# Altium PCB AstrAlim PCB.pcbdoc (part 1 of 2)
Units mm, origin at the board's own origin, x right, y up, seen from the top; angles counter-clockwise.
Board outline 123.28 x 79.48 mm, 4 copper layers (Top Layer, Inner1, Inner2, Bottom Layer); 156 components, 74 nets, 482 pads, 222 vias.
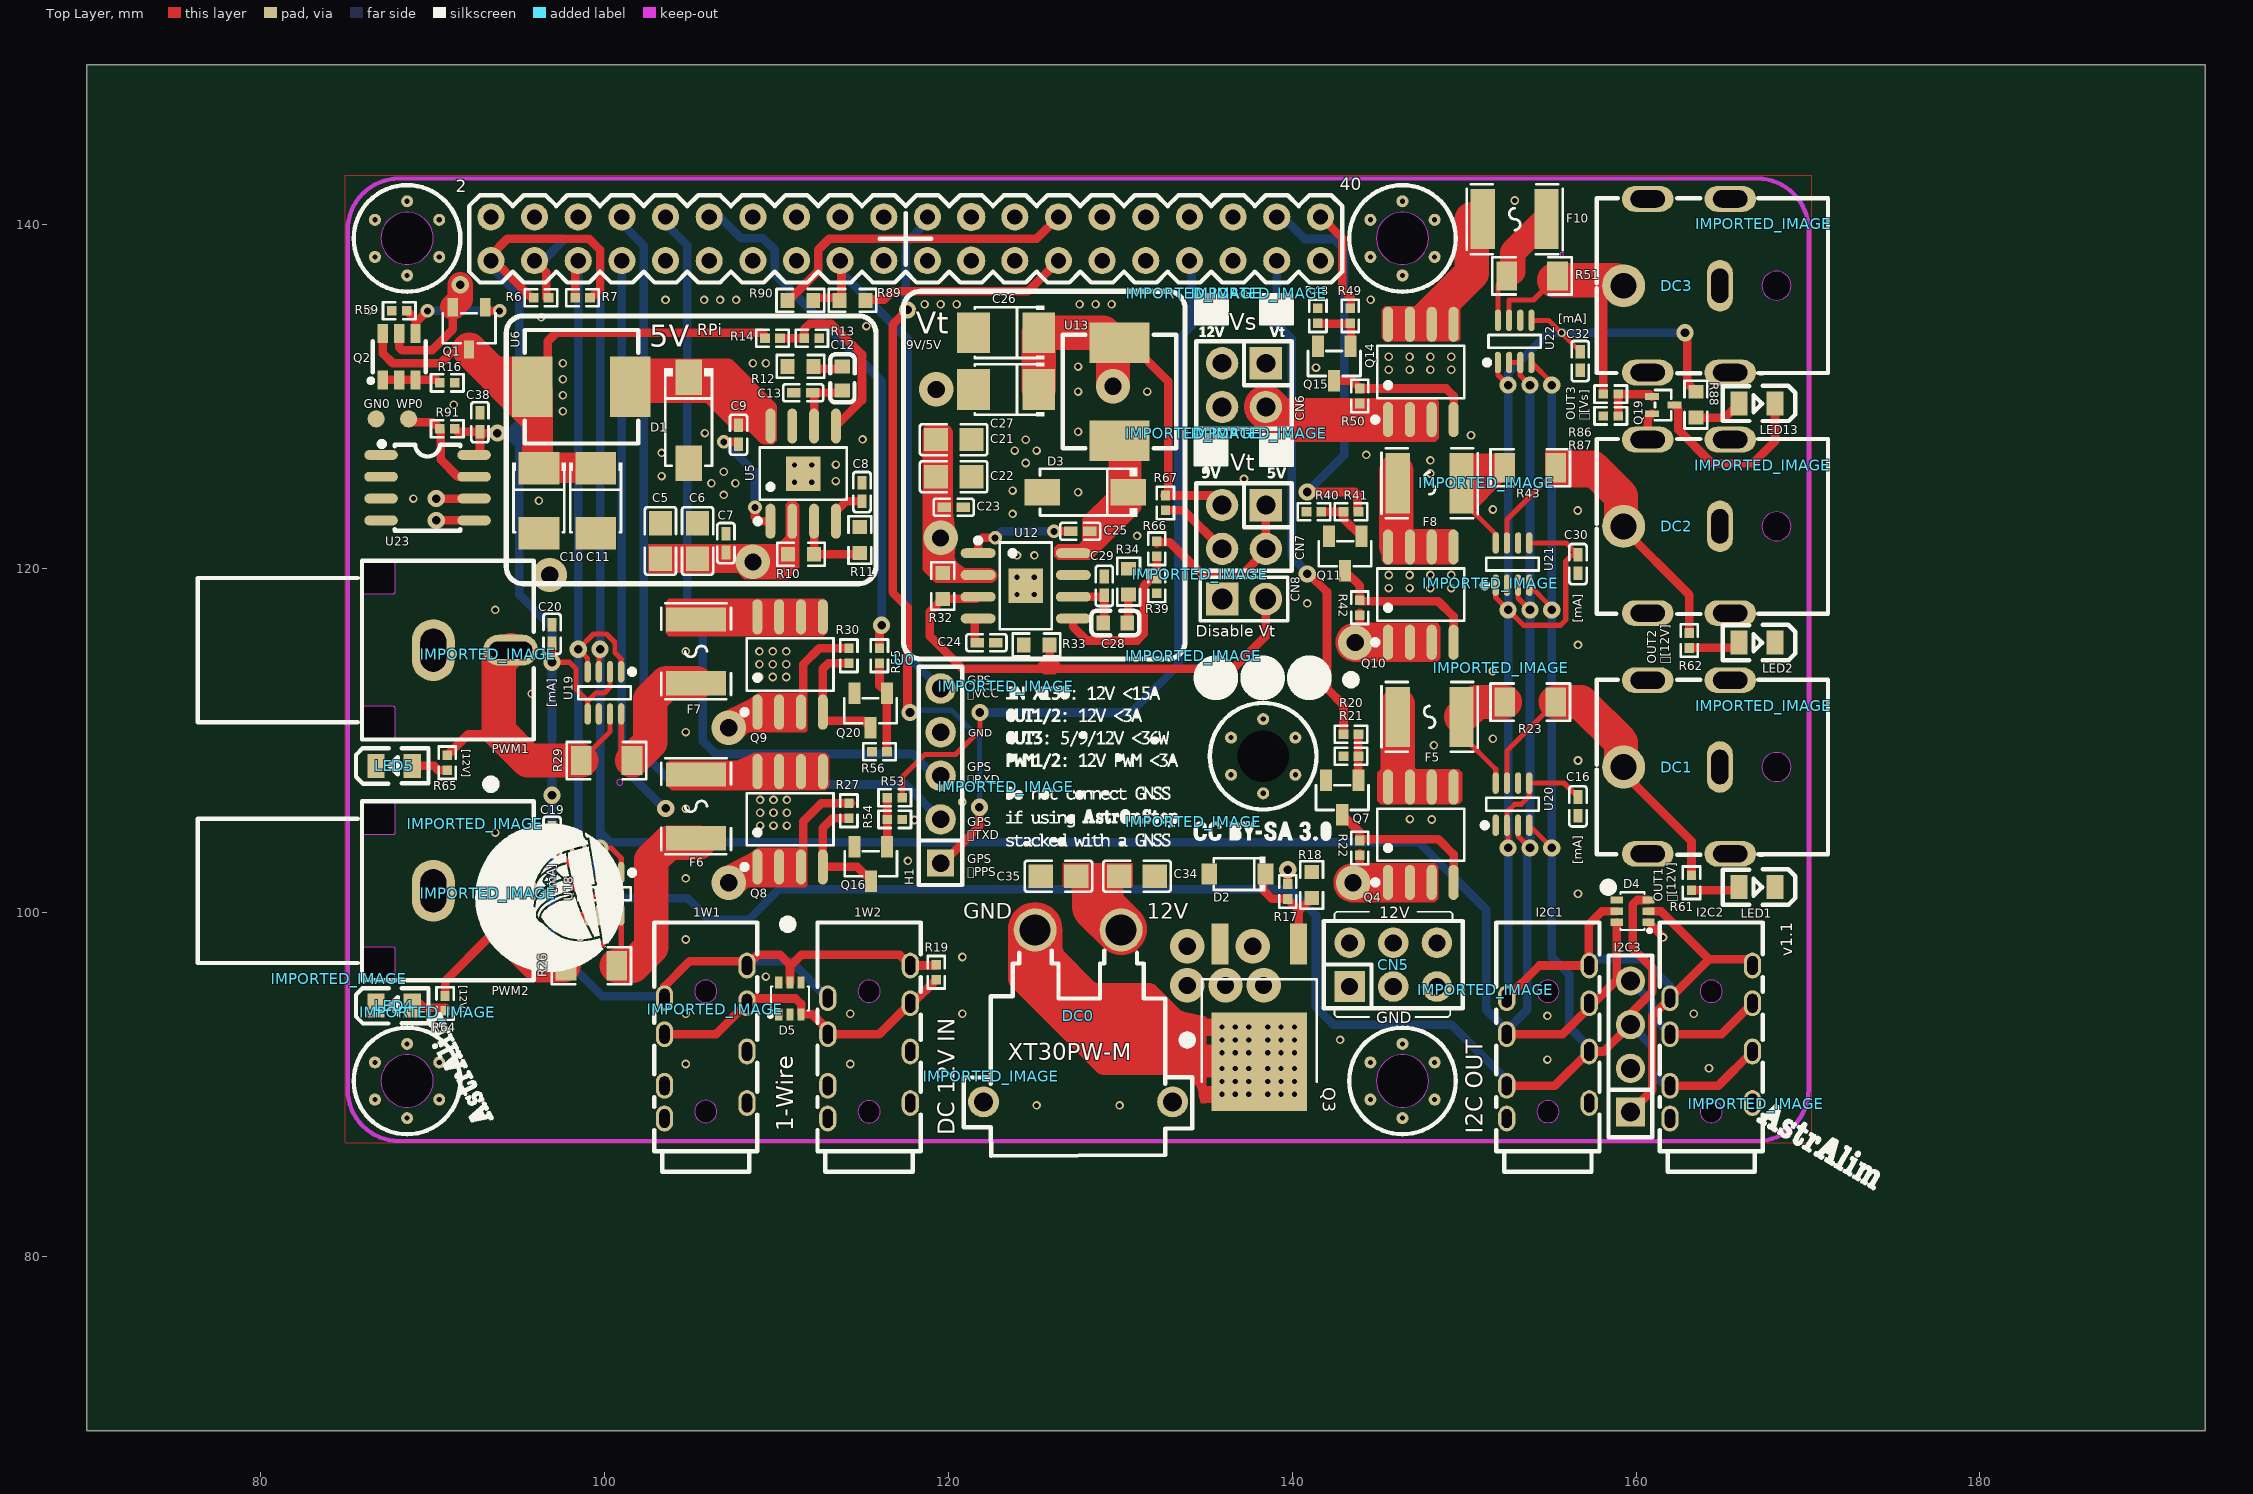
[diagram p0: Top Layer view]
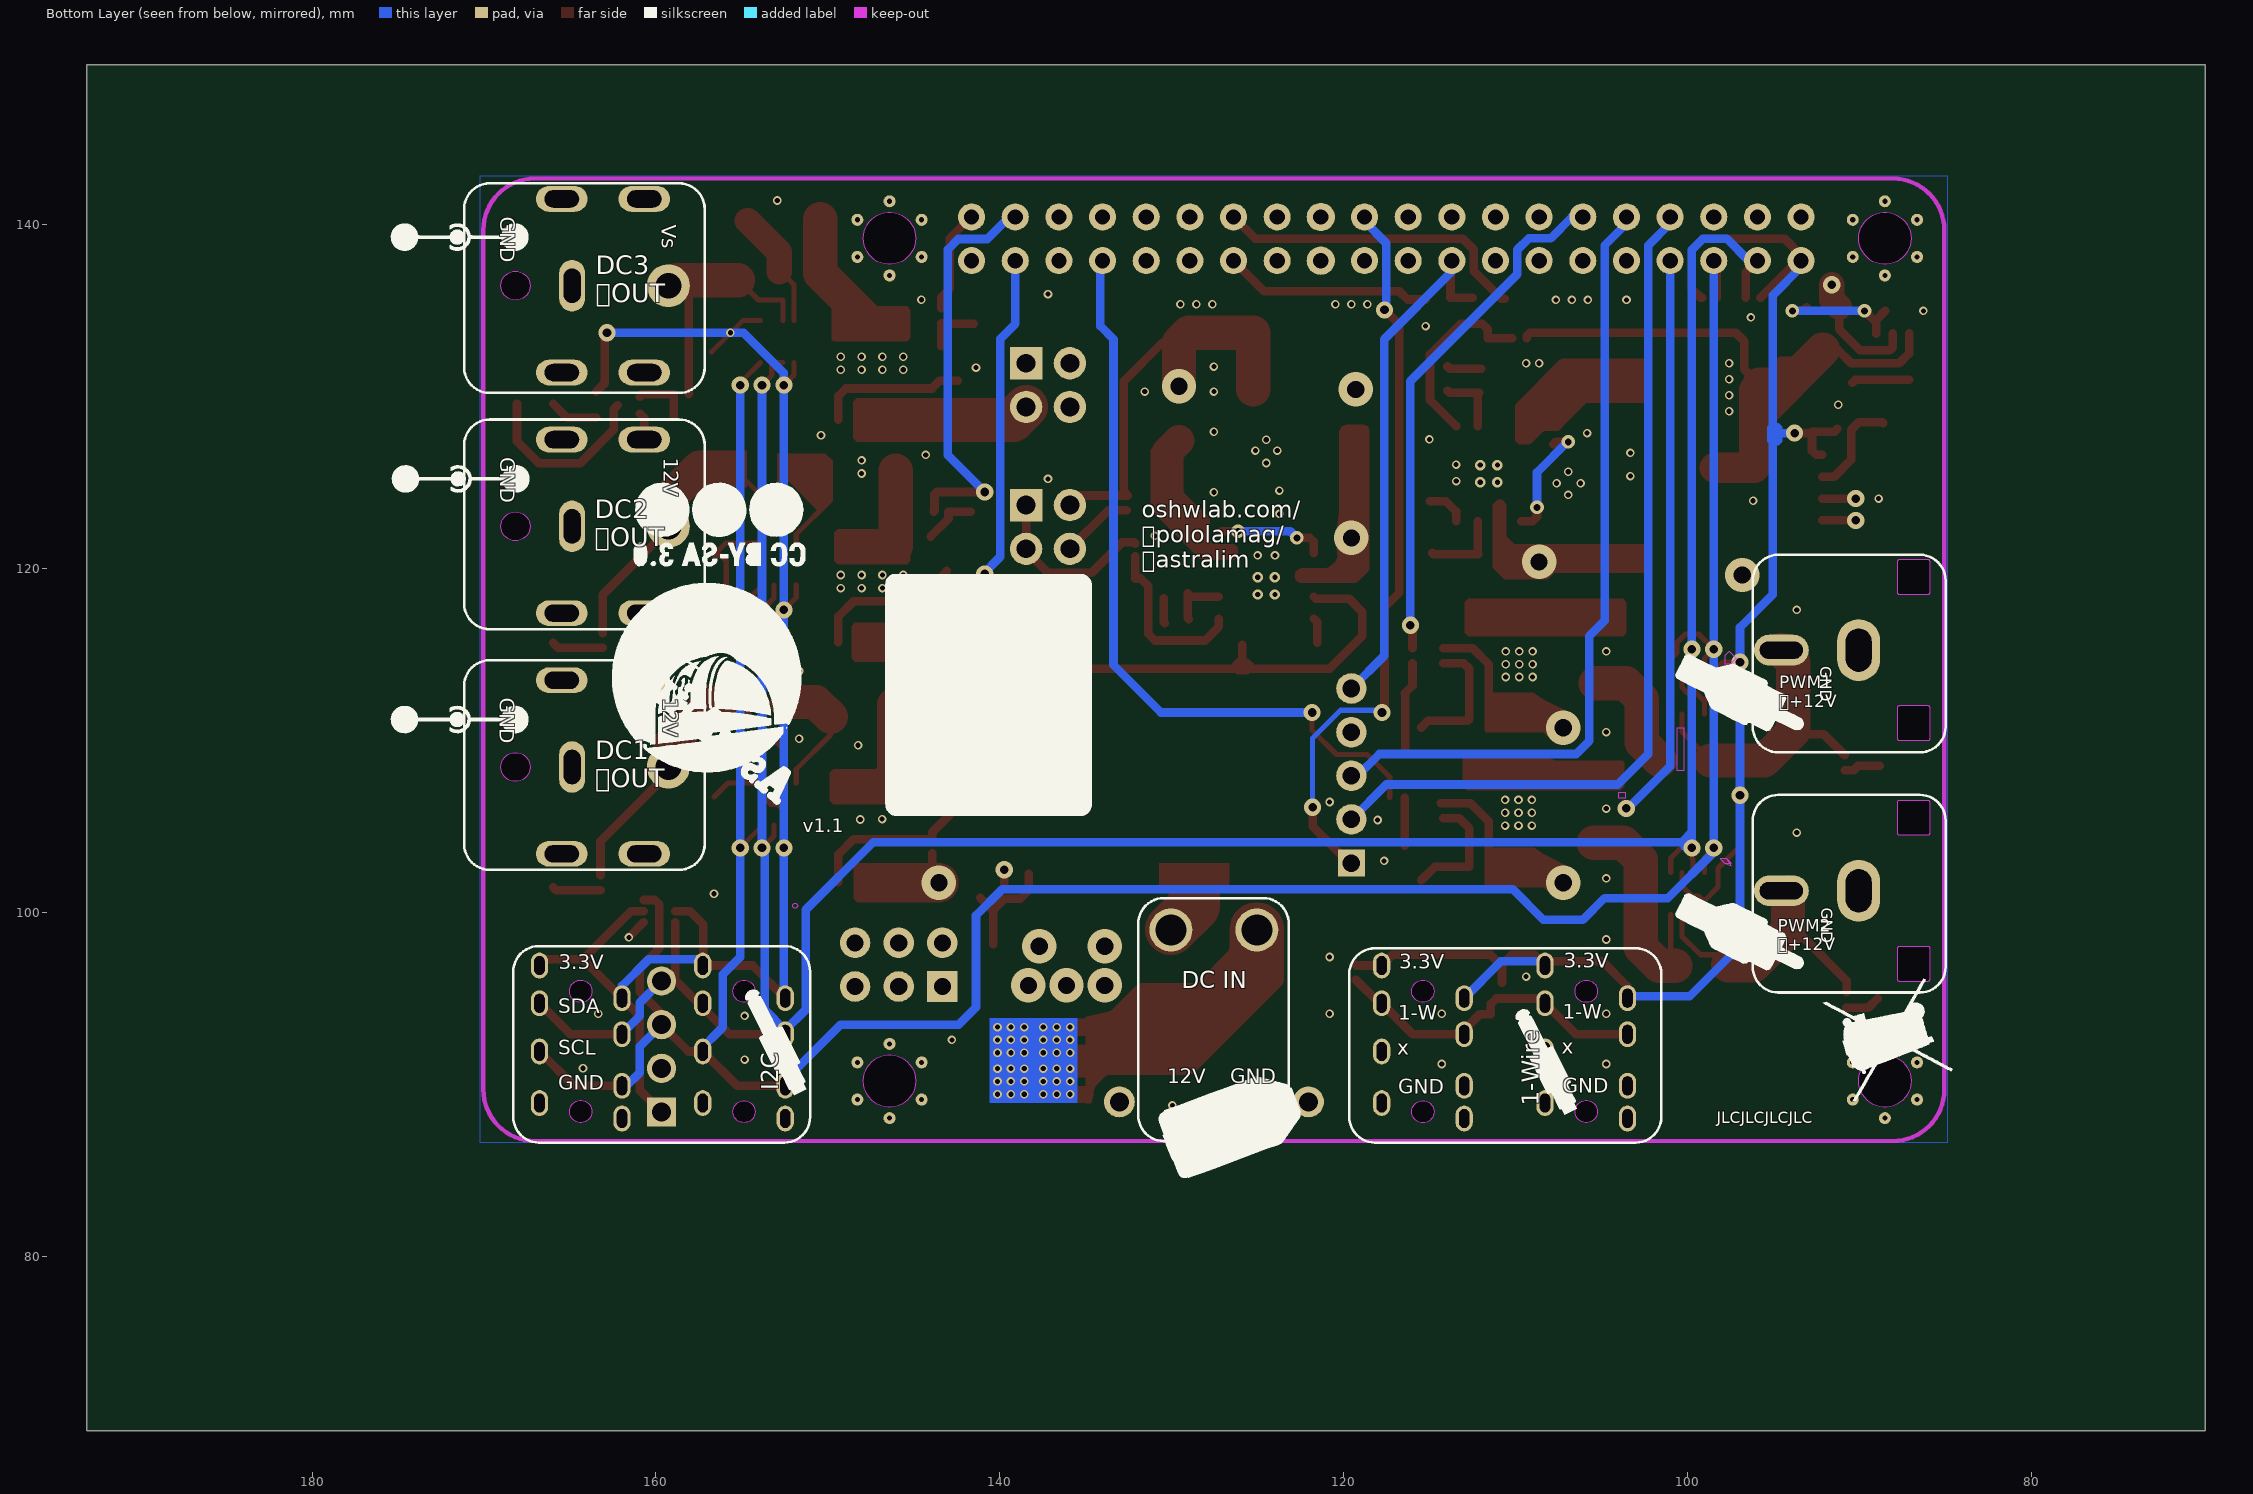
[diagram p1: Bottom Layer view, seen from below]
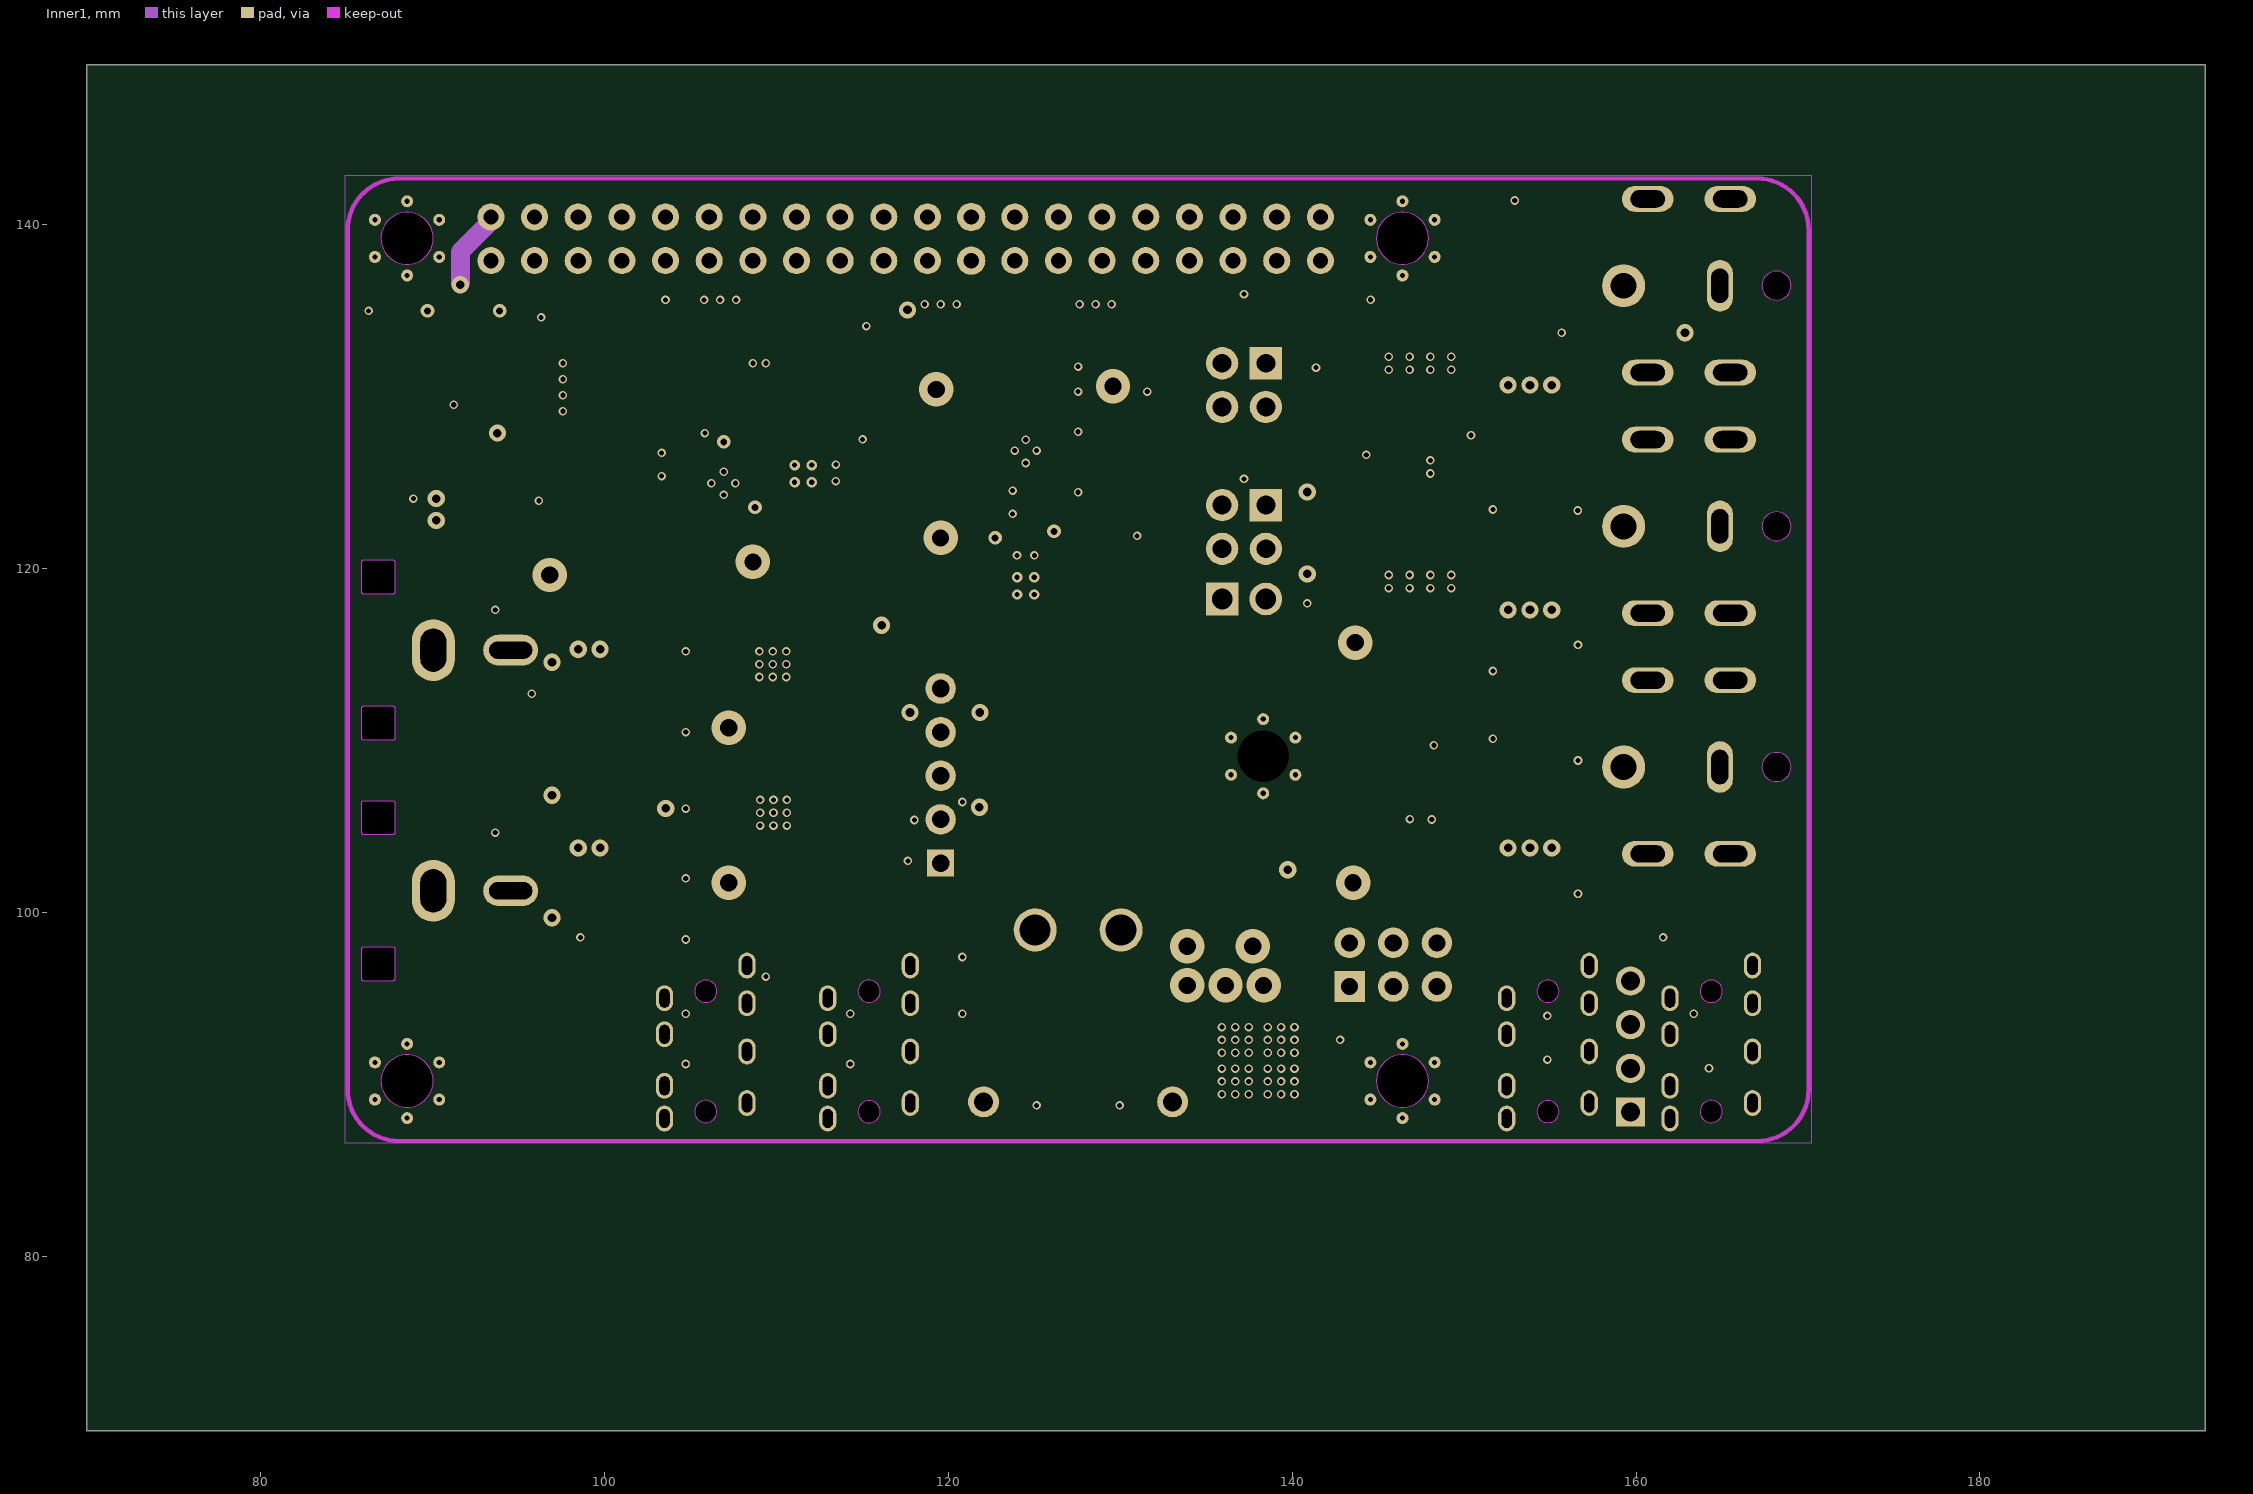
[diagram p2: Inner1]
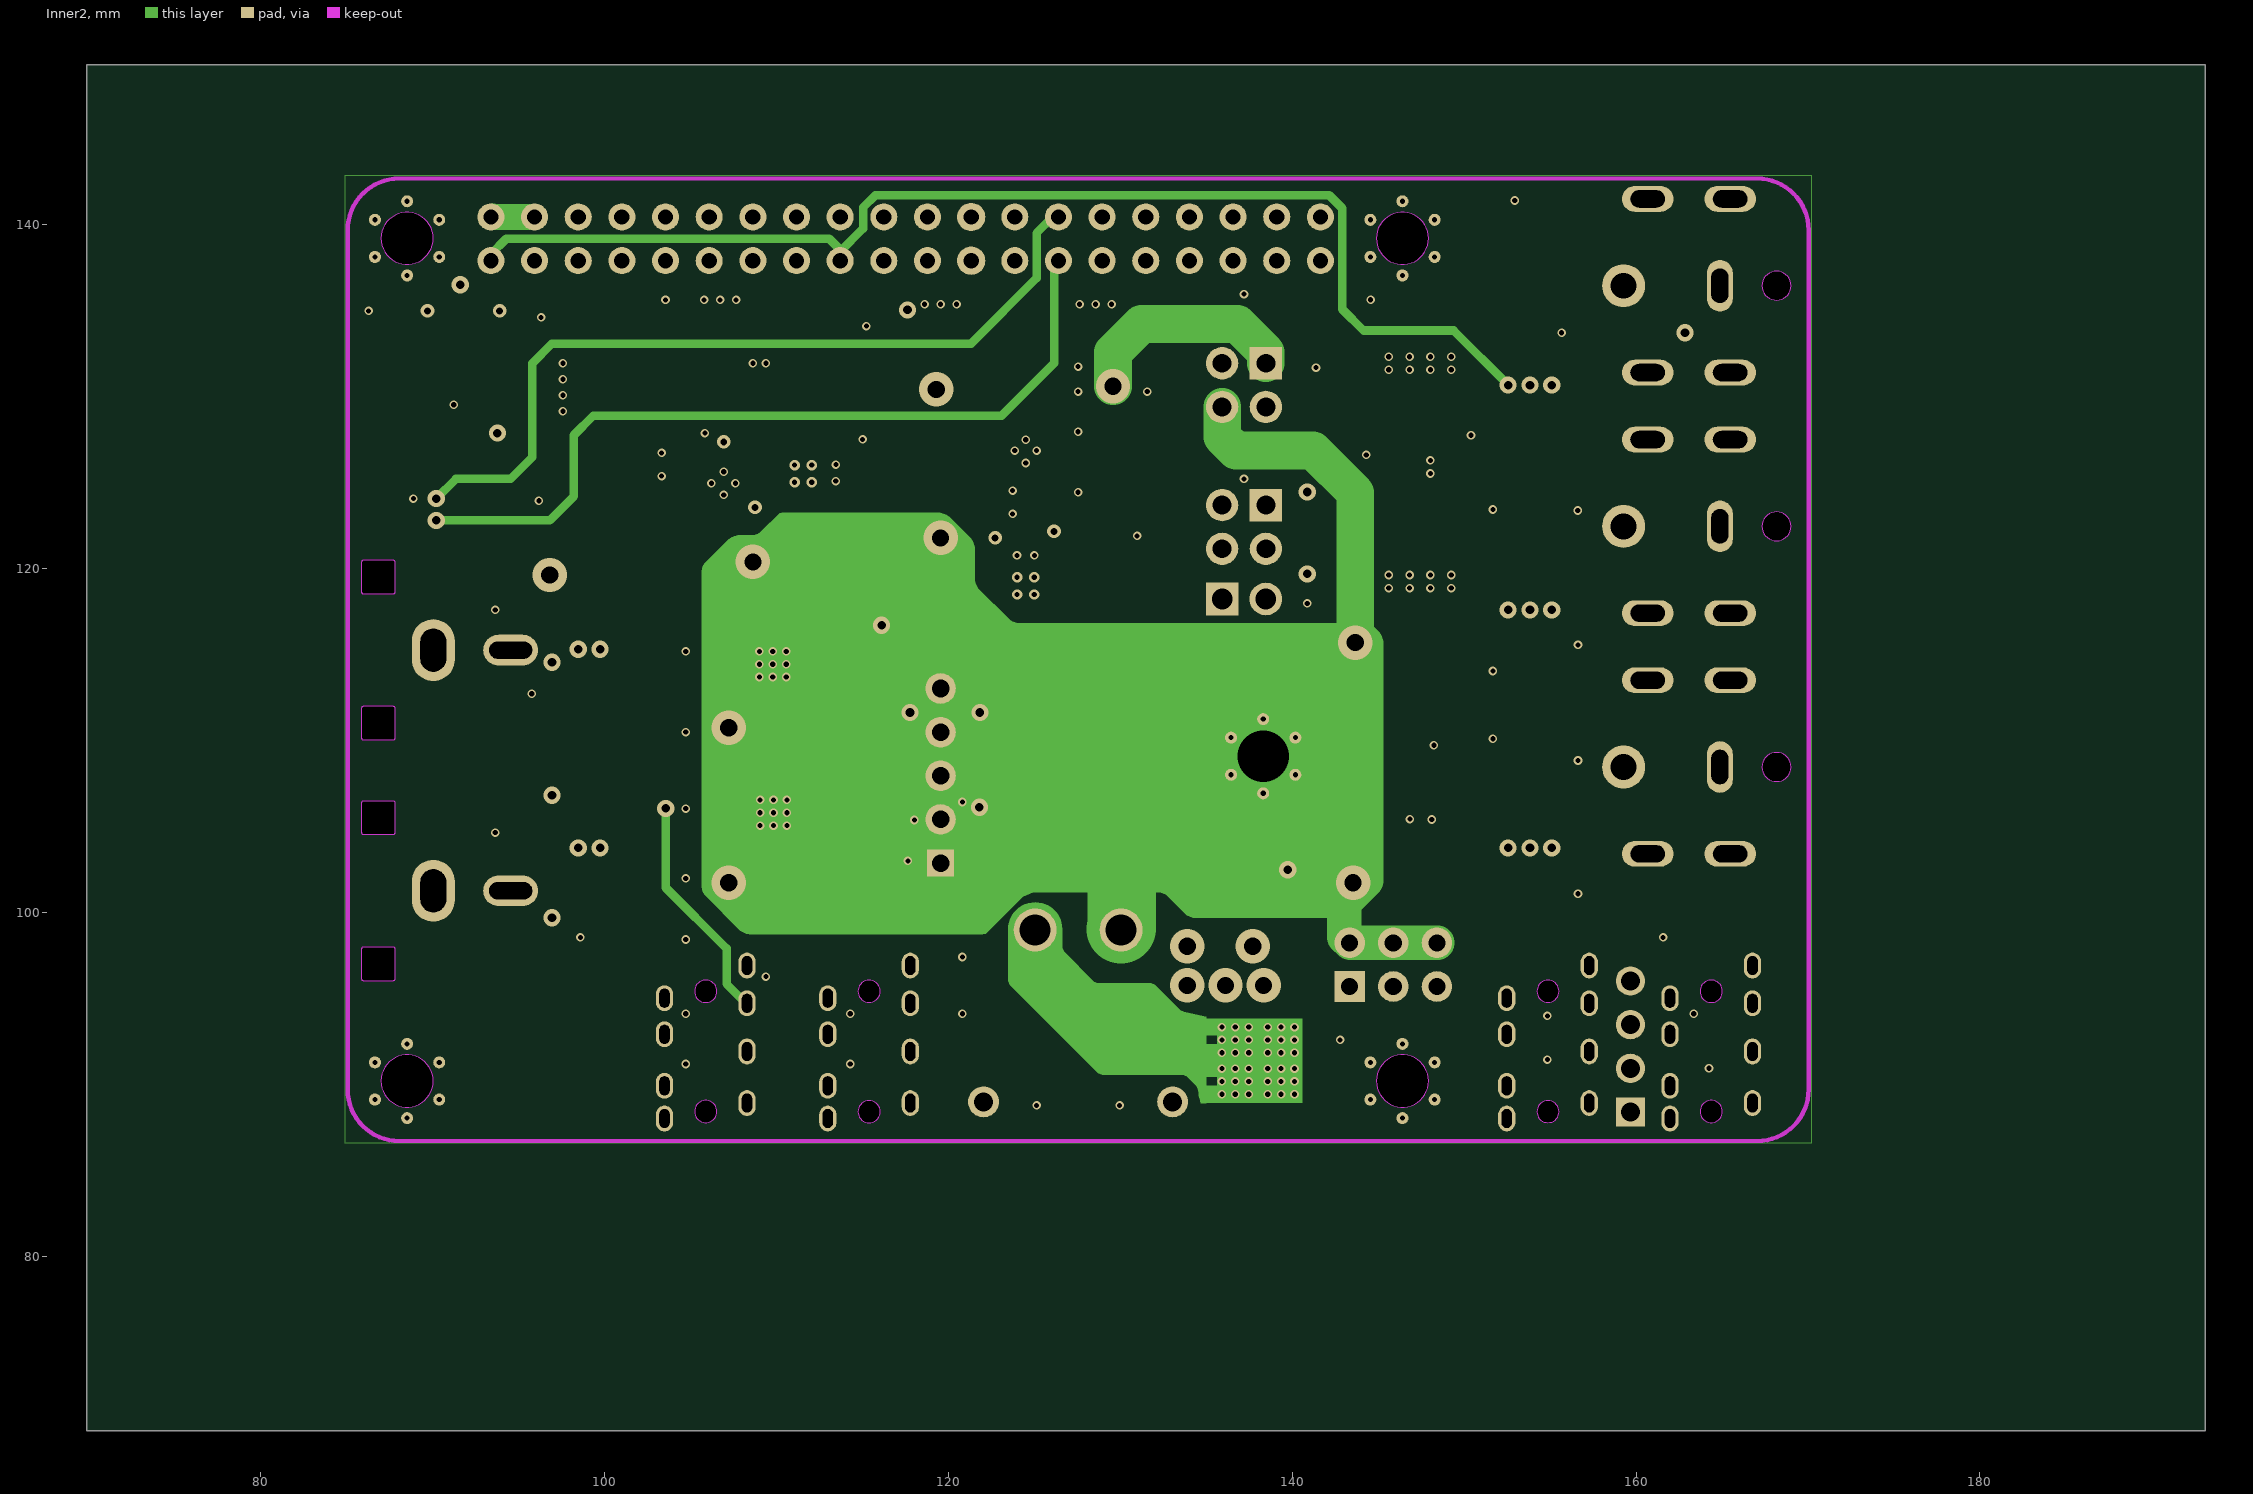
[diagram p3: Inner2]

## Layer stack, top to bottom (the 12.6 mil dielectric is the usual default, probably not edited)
Top Layer: signal copper (thickness not stored)
Dielectric: dielectric 0.32, FR-4, Dk 4.8
Inner1: signal copper (thickness not stored)
Dielectric: dielectric 0.32, FR-4, Dk 4.8
Inner2: signal copper (thickness not stored)
Dielectric: dielectric 0.32, FR-4, Dk 4.8
Bottom Layer: signal copper (thickness not stored)

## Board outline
193.13,69.85 69.85,69.85 69.85,149.333 193.13,149.333

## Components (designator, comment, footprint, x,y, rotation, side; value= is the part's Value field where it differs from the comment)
1W1 "PJ-35372" audio-th_pj-35372 105.877,92.462 r180 top
1W2 "PJ-35372" audio-th_pj-35372 115.377,92.462 r180 top
C5 "CL21A475KAQNNNE" C0805 103.242,121.614 r270 top
C6 "CL21A475KAQNNNE" C0805 105.401,121.614 r270 top
C7 "CL05B103KB5NNNC" C0402 107.052,121.487 r270 top
C8 "CL05B103KB5NNNC" C0402 114.967,124.46 r270 top
C9 "CL05B103KB5NNNC" C0402 107.784,127.793 r90 top
C10 "CA45-B-16V-47uF-K" CAP-SMD_L3.5-W2.8-R-RD 96.171,123.952 r90 top
C11 "CA45-B-16V-47uF-K" CAP-SMD_L3.5-W2.8-R-RD 99.473,123.952 r90 top
C12 "0603B222K500NT" C0603 113.824,131.064 r270 top
C13 "0402CG220J500NT" C0402 111.546,130.23 r0 top
C16 "CL05B104KO5NNNC" C0402 156.623,106.172 r270 top
C19 "CL05B104KO5NNNC" C0402 96.933,104.394 r90 top
C20 "CL05B104KO5NNNC" C0402 96.933,116.205 r90 top
C21 "CL21A475KAQNNNE" C0805 120.301,127.508 r180 top
C22 "CL21A475KAQNNNE" C0805 120.301,125.349 r180 top
C23 "CL05B103KB5NNNC" C0402 120.301,123.571 r180 top
C24 "CL05B103KB5NNNC" C0402 122.206,115.697 r180 top
C25 "CL05B103KB5NNNC" C0402 127.667,122.174 r0 top
C26 "CA45-B-16V-47uF-K" CAP-SMD_L3.5-W2.8-R-RD 123.349,133.731 r0 top
C27 "CA45-B-16V-47uF-K" CAP-SMD_L3.5-W2.8-R-RD 123.349,130.429 r0 top
C28 "0603B222K500NT" C0603 129.699,116.84 r180 top
C29 "0402CG220J500NT" C0402 129.064,118.999 r270 top
C30 "CL05B104KO5NNNC" C0402 156.623,120.269 r270 top
C32 "CL05B104KO5NNNC" C0402 156.75,132.08 r270 top
C34 "CL21A226MAQNNNE_C45783" C0805 130.969,102.108 r180 top
C35 "CL21A226MAQNNNE_C45783" C0805 126.397,102.108 r0 top
C38 "CL05B104KO5NNNC" C0402 92.742,128.524 r270 top
CN5 "PM254-2-03-Z-8.5" hdr-th_6p-p2.54-v-f-r2-c3-s2.54 145.877,96.962 r0 top
CN6 "PH-00068" HDR-TH_4P-P2.54-V-M-R2-C2-S2.54 137.192,130.683 r180 top
CN7 "PH-00068" HDR-TH_4P-P2.54-V-M-R2-C2-S2.54 137.192,122.428 r180 top
CN8 "PZ254V-11-02P" hdr-th_2p-p2.54-v-m 137.192,118.237 r0 top
D1 "SS54_C22452" SMA_L4.4-W2.8-LS5.4-R-RD 104.881,128.635 r270 top
D2 "MM1Z15_C86235" SOD-123_L2.7-W1.6-LS3.7-RD 136.811,102.235 r180 top
D3 "SS54_C22452" SMA_L4.4-W2.8-LS5.4-R-RD 127.966,124.451 r180 top
D4 "BAV99S,115" SOT-363_L2.0-W1.3-P0.65-LS2.1-TL 159.798,100.076 r180 top
D5 "BAV99S,115" SOT-363_L2.0-W1.3-P0.65-LS2.1-TL 110.776,94.996 r90 top
DC0 "XT30PW-M" CONN-TH_XT30PW-M 127.54,93.98 r0 top
DC1 "DC-042C-W-2.0" dc-in-th_dc-042c-w-2.0 162.377,108.462 r180 top
DC2 "DC-042C-W-2.0" dc-in-th_dc-042c-w-2.0 162.377,122.462 r180 top
DC3 "DC-042C-W-2.0" dc-in-th_dc-042c-w-2.0 162.377,136.462 r180 top
F5 "SMD1812P300SLR/24_C2892380" F1812 147.987,111.379 r180 top
F6 "SMD1812P300SLR/24_C2892380" F1812 105.315,106.172 r90 top
F7 "SMD1812P300SLR/24_C2892380" F1812 105.315,115.189 r90 top
F8 "SMD1812P300SLR/24_C2892380" F1812 147.987,124.968 r180 top
F10 "SMD1812P300SLR/24_C2892380" F1812 152.94,140.335 r180 top
GN0 "Test-Point" test-point-0.5mm 86.703,128.719 r180 top
H1 "2.54-1*5P母" hdr-th_5p-p2.54-v-f 119.539,107.95 r90 top
I2C1 "PJ-35372" audio-th_pj-35372 154.877,92.462 r180 top
I2C2 "PJ-35372" audio-th_pj-35372 164.377,92.462 r180 top
I2C3 "2.54-1*4P母" hdr-th_4p-p2.54-v-f 159.671,92.202 r90 top
IMPORTED_IMAGE "IMPORTED_IMAGE" IMPORTED_IMAGE 167.007,88.865 r0 top
IMPORTED_IMAGE "IMPORTED_IMAGE" IMPORTED_IMAGE 92.475,105.175 r0 top
IMPORTED_IMAGE "IMPORTED_IMAGE" IMPORTED_IMAGE 134.295,136.017 r0 top
IMPORTED_IMAGE "IMPORTED_IMAGE" IMPORTED_IMAGE 138.089,136.017 r0 top
IMPORTED_IMAGE "IMPORTED_IMAGE" IMPORTED_IMAGE 152.149,114.23 r0 top
IMPORTED_IMAGE "IMPORTED_IMAGE" IMPORTED_IMAGE 151.26,95.514 r0 top
IMPORTED_IMAGE "IMPORTED_IMAGE" IMPORTED_IMAGE 93.223,101.114 r0 top
IMPORTED_IMAGE "IMPORTED_IMAGE" IMPORTED_IMAGE 167.418,112.014 r0 top
IMPORTED_IMAGE "IMPORTED_IMAGE" IMPORTED_IMAGE 167.418,140.081 r0 top
IMPORTED_IMAGE "IMPORTED_IMAGE" IMPORTED_IMAGE 167.361,126.013 r0 top
IMPORTED_IMAGE "IMPORTED_IMAGE" IMPORTED_IMAGE 151.547,119.158 r0 top
IMPORTED_IMAGE "IMPORTED_IMAGE" IMPORTED_IMAGE 84.567,96.147 r0 top
IMPORTED_IMAGE "IMPORTED_IMAGE" IMPORTED_IMAGE 122.495,90.465 r0 top
IMPORTED_IMAGE "IMPORTED_IMAGE" IMPORTED_IMAGE 93.223,115.018 r0 top
IMPORTED_IMAGE "IMPORTED_IMAGE" IMPORTED_IMAGE 134.271,127.889 r0 top
IMPORTED_IMAGE "IMPORTED_IMAGE" IMPORTED_IMAGE 138.081,127.866 r0 top
IMPORTED_IMAGE "IMPORTED_IMAGE" IMPORTED_IMAGE 106.433,94.369 r0 top
IMPORTED_IMAGE "IMPORTED_IMAGE" IMPORTED_IMAGE 123.349,113.157 r0 top
IMPORTED_IMAGE "IMPORTED_IMAGE" IMPORTED_IMAGE 123.349,107.315 r0 top
IMPORTED_IMAGE "IMPORTED_IMAGE" IMPORTED_IMAGE 151.301,124.99 r0 top
IMPORTED_IMAGE "IMPORTED_IMAGE" IMPORTED_IMAGE 134.271,105.283 r0 top
IMPORTED_IMAGE "IMPORTED_IMAGE" IMPORTED_IMAGE 134.273,114.935 r0 top
IMPORTED_IMAGE "IMPORTED_IMAGE" IMPORTED_IMAGE 134.652,119.69 r0 top
IMPORTED_IMAGE "IMPORTED_IMAGE" IMPORTED_IMAGE 89.704,94.208 r0 top
LED1 "NCD0805R1_C84256" LED0805-R-RD 167.037,101.473 r180 top
LED2 "NCD0805R1_C84256" LED0805-R-RD 167.037,115.697 r180 top
LED4 "NCD0805R1_C84256" LED0805-R-RD 87.75,94.581 r0 top
LED5 "NCD0805R1_C84256" LED0805-R-RD 87.75,108.532 r0 top
LED13 "NCD0805R1_C84256" LED0805-R-RD 167.037,129.605 r180 top
PWM1 "AV-5" rcj-04 91.977,115.262 r270 top
PWM2 "AV-5" rcj-04 91.977,101.262 r270 top
Q1 "DMMT5401-7-F" SOT-23-6_L2.9-W1.6-P0.95-LS2.8-BR 88.043,132.334 r270 top
Q2 "AP2317A" SOT-23-3_L2.9-W1.6-P1.90-LS2.8-BR 92.107,133.985 r90 top
Q3 "DMTH4004LK3-13" TO-252-2_L6.6-W6.1-P4.58-LS9.9-TL 138.081,94.742 r270 top
Q4 "NCE30P12S" soic-8_l4.9-w3.9-p1.27-ls6.0-bl 147.479,104.521 r0 top
Q7 "MMBT3904_C20526" SOT-23-3_L2.9-W1.3-P1.90-LS2.4-BR 142.909,106.684 r90 top
Q8 "NCE30P12S" SOIC-8_L4.9-W3.9-P1.27-LS6.0-BL 110.783,105.421 r0 top
Q9 "NCE30P12S" SOIC-8_L4.9-W3.9-P1.27-LS6.0-BL 110.783,114.427 r0 top
Q10 "NCE30P12S" soic-8_l4.9-w3.9-p1.27-ls6.0-bl 147.479,118.491 r0 top
Q11 "MMBT3904_C20526" SOT-23-3_L2.9-W1.3-P1.90-LS2.4-BR 143.077,120.878 r90 top
Q14 "NCE30P12S" SOIC-8_L4.9-W3.9-P1.27-LS6.0-BL 147.479,131.445 r0 top
Q15 "MMBT3904_C20526" SOT-23-3_L2.9-W1.3-P1.90-LS2.4-BR 142.44,131.94 r90 top
Q16 "MMBT3904_C20526" SOT-23-3_L2.9-W1.3-P1.90-LS2.4-BR 115.479,102.828 r90 top
Q19 "MMBT3904TT1G" SC-75-3_L1.6-W0.8-P1.00-LS1.6-BR 161.576,129.517 r180 top
Q20 "MMBT3904_C20526" SOT-23-3_L2.9-W1.3-P1.90-LS2.4-BR 115.468,111.74 r90 top
R6 "0402WGF1002TCE" R0402 96.298,135.763 r180 top
R7 "0402WGF1002TCE" R0402 98.711,135.763 r0 top
R10 "AC0603FR-07665KL" R0603 111.411,120.84 r180 top
R11 "0603WAF1303T5E" R0603 114.84,121.666 r270 top
R12 "0603WAF3902T5E" R0603 111.389,131.769 r180 top
R13 "0402WGF1961TCE" R0402 112.046,133.413 r180 top
R14 "0402WGF1022TCE" R0402 109.76,133.413 r180 top
R16 "0402WGF1002TCE" R0402 90.837,130.81 r180 top
R17 "0402WGF1001TCE" R0402 139.732,101.219 r270 top
R18 "0603WAF4703T5E" R0603 141.129,101.6 r270 top
R19 "0402WGF4701TCE" R0402 119.285,96.52 r90 top
R20 "0402WGF1002TCE" R0402 143.415,109.093 r0 top
R21 "0402WGF1001TCE" R0402 143.415,110.363 r0 top
R22 "0402WGF1001TCE" R0402 143.923,103.759 r270 top
R23 "MFJ06HR010FT" R1206 153.847,112.241 r180 top
R26 "MFJ06HR010FT" R1206 99.219,96.901 r0 top
R27 "0402WGF1001TCE" R0402 114.205,105.918 r90 top
R29 "MFJ06HR010FT" R1206 100.108,108.839 r0 top
R30 "0402WGF1001TCE" R0402 114.205,114.935 r90 top
R32 "AC0603FR-07665KL" R0603 119.666,118.999 r90 top
R33 "0603WAF8202T5E" R0603 125.127,115.57 r0 top
R34 "0603WAF3902T5E" R0603 130.481,119.244 r90 top
R39 "0402WGF1961TCE" R0402 132.112,118.999 r90 top
R40 "0402WGF1002TCE" R0402 141.256,123.317 r0 top
R41 "0402WGF1001TCE" R0402 143.415,123.317 r180 top
R42 "0402WGF1001TCE" R0402 143.923,117.729 r270 top
R43 "MFJ06HR010FT" R1206 153.847,125.872 r180 top
R48 "0402WGF1002TCE" R0402 141.49,134.712 r270 top
R49 "0402WGF1001TCE" R0402 143.372,134.712 r270 top
R50 "0402WGF1001TCE" R0402 143.923,130.048 r270 top
R51 "MFJ06HR010FT" R1206 153.956,137.033 r180 top
R53 "0402WGF1001TCE" R0402 116.872,106.68 r180 top
R54 "0402WGF1002TCE" R0402 116.872,105.41 r180 top
R55 "0402WGF1001TCE" R0402 115.983,114.935 r270 top
R56 "0402WGF1002TCE" R0402 115.983,109.347 r0 top
R59 "0402WGF4702TCE" R0402 88.043,135.001 r0 top
R61 "0402WGF4700TCE" R0402 163.227,101.727 r270 top
R62 "0402WGF4700TCE" R0402 163.1,115.824 r270 top
R64 "0402WGF4700TCE" R0402 90.71,94.708 r270 top
R65 "0402WGF4700TCE" R0402 90.837,108.712 r270 top
R66 "0402WGF1022TCE" R0402 132.112,121.158 r90 top
R67 "0402WGF1002TCE" R0402 132.62,123.825 r90 top
R86 "0402WGF1002TCE" R0402 158.528,130.158 r180 top
R87 "0402WGF1002TCE" R0402 158.528,128.888 r0 top
R88 "0603WAF680JT5E" R0603 163.481,129.54 r270 top
R89 "0603WAF3901T5E" R0603 114.419,135.612 r180 top
R90 "0603WAF3901T5E" R0603 111.379,135.612 r0 top
R91 "0402WGF1001TCE" R0402 90.837,128.143 r0 top
U0 "RASPI HAT FULL" rasberrypi-3-hat-ext 93.377,140.462 r0 top
U5 "TPS54531DDAR" SOIC-8_L5.0-W4.0-P1.27-LS6.0-BL-EP2.0 111.546,125.531 r0 top
U6 "CYA0630-4.7UH" IND-SMD_L7.2-W6.6_GPSR07X0 98.64,130.587 r180 top
U12 "TPS54531DDAR" SOIC-8_L5.0-W4.0-P1.27-LS6.0-BL-EP2.0 124.492,118.999 r270 top
U13 "CYA0630-4.7UH" IND-SMD_L7.2-W6.6_GPSR07X0 129.953,130.302 r90 top
U18 "INA219AIDCNR" sot-23-8_l3.0-w1.7-p0.65-ls2.8-br 99.981,101.092 r90 top
U19 "INA219AIDCNR" sot-23-8_l3.0-w1.7-p0.65-ls2.8-br 99.981,112.776 r90 top
U20 "INA219AIDCNR" sot-23-8_l3.0-w1.7-p0.65-ls2.8-br 152.813,106.299 r270 top
U21 "INA219AIDCNR" sot-23-8_l3.0-w1.7-p0.65-ls2.8-br 152.813,120.269 r270 top
U22 "INA219AIDCNR" sot-23-8_l3.0-w1.7-p0.65-ls2.8-br 152.94,133.223 r270 top
U23 "AT24C32D-SSHM-T" SOIC-8_L5.0-W4.0-P1.27-LS6.0-BL 89.694,124.714 r270 top
WP0 "Test-Point" test-point-0.5mm 88.592,128.719 r180 top

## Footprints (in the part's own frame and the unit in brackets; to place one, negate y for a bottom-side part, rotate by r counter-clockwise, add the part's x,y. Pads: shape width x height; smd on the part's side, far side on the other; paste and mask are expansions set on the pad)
audio-th_pj-35372 [mm]
  oval 1x1.5 hole 0.6 slot 1.1 at 90 deg: 1(-2.4,3.55) 2(-2.4,0.55) 3(-2.4,-2.25) 4(-2.4,-4.45) 5(2.4,4.45) 6(2.4,2.55) 7(2.4,-0.45) 8(2.4,-2.55)
  Multi-Layer board cut-out: -0.65,4.05 -0.586,3.768 -0.405,3.542 -0.145,3.416 0.145,3.416 0.405,3.542 0.586,3.768 0.65,4.05 0.65,4.05 0.586,4.332 0.405,4.558 0.145,4.684 -0.145,4.684 -0.405,4.558 -0.586,4.332 -0.65,4.05
  Multi-Layer board cut-out: -0.65,-2.95 -0.586,-3.232 -0.405,-3.458 -0.145,-3.584 0.145,-3.584 0.405,-3.458 0.586,-3.232 0.65,-2.95 0.65,-2.95 0.586,-2.668 0.405,-2.442 0.145,-2.316 -0.145,-2.316 -0.405,-2.442 -0.586,-2.668 -0.65,-2.95
  Multi-Layer keep-out region: -0.65,4.05 -0.586,3.768 -0.405,3.542 -0.145,3.416 0.145,3.416 0.405,3.542 0.586,3.768 0.65,4.05 0.65,4.05 0.586,4.332 0.405,4.558 0.145,4.684 -0.145,4.684 -0.405,4.558 -0.586,4.332 -0.65,4.05
  Multi-Layer keep-out region: -0.65,-2.95 -0.586,-3.232 -0.405,-3.458 -0.145,-3.584 0.145,-3.584 0.405,-3.458 0.586,-3.232 0.65,-2.95 0.65,-2.95 0.586,-2.668 0.405,-2.442 0.145,-2.316 -0.145,-2.316 -0.405,-2.442 -0.586,-2.668 -0.65,-2.95
  silkscreen extent -3,-6.95 3,7.55
C0402 [mm]
  rect 0.79x0.54 smd: 1(-0.545,0) 2(0.545,0)
  silkscreen extent -1.17,-0.5 1.17,0.5
C0603 [mm]
  rect 0.8x0.9 smd: 1(-0.7,0) 2(0.7,0)
  silkscreen extent -1.41,-0.71 1.39,0.72
C0805 [mm]
  rect 1.41x1.35 smd: 1(-1.03,0) 2(1.03,0)
  silkscreen extent -1.96,-0.9 1.96,0.9
CAP-SMD_L3.5-W2.8-R-RD [mm]
  rect 1.9x2.376 smd: 1(1.899,0) 2(-1.899,0)
  silkscreen extent -1.83,-1.55 2.21,1.55
CONN-TH_XT30PW-M [mm]
  round 2.5 hole 1.8: 1(-2.5,5) 2(2.5,5)
  round 1.8 hole 1.1: 3(5.5,-5) 4(-5.5,-5)
  silkscreen extent -6.65,-8.15 6.65,3.81
dc-in-th_dc-042c-w-2.0 [mm]
  oval 3x1.5 hole 1 slot 2 at 0 deg: 2(-3.1,5.05) 2(-3.1,-5.05) 2(1.7,5.05) 2(1.7,-5.05)
  oval 1.5x3 hole 1 slot 2 at 90 deg: 3(-2.5,0)
  round 2.5 hole 1.5: 4(3.1,0)
  Multi-Layer board cut-out: -6.65,0 -6.533,-0.421 -6.223,-0.729 -5.8,-0.841 -5.378,-0.729 -5.067,-0.421 -4.95,0 -4.95,0 -5.067,0.421 -5.378,0.729 -5.8,0.841 -6.223,0.729 -6.533,0.421 -6.65,0
  Multi-Layer keep-out region: -6.65,0 -6.533,-0.421 -6.223,-0.729 -5.8,-0.841 -5.378,-0.729 -5.067,-0.421 -4.95,0 -4.95,0 -5.067,0.421 -5.378,0.729 -5.8,0.841 -6.223,0.729 -6.533,0.421 -6.65,0
  silkscreen extent -8.79,-5.08 4.67,5.1
F1812 [mm]
  rect 1.407x3.499 smd: 1(-1.853,0) 2(1.853,0)
  silkscreen extent -2.79,-2.03 2.79,2.03
hdr-th_2p-p2.54-v-m [mm]
  rect 1.905x1.905 hole 1.2: 1(-1.27,0)
  round 1.905 hole 1.2: 2(1.27,0)
  silkscreen extent -2.54,-1.27 2.54,1.27
hdr-th_4p-p2.54-v-f [mm]
  rect 1.7x1.7 hole 1.1: 1(-3.81,0)
  round 1.7 hole 1.1: 2(-1.27,0) 3(1.27,0) 4(3.81,0)
  silkscreen extent -5.29,-1.27 5.29,1.27
HDR-TH_4P-P2.54-V-M-R2-C2-S2.54 [mil]
  rect 74x74 hole 43.31: 1(-50,-50)
  round 74 hole 43.31: 2(-50,50) 3(50,-50) 4(50,50)
  silkscreen extent -109,-100 109,100
hdr-th_5p-p2.54-v-f [mil]
  rect 62x62 hole 40.16: 1(-200,0)
  round 70 hole 40.16: 2(-100,0) 3(0,0) 4(100,0) 5(200,0)
  silkscreen extent -250,-50 250,50
hdr-th_6p-p2.54-v-f-r2-c3-s2.54 [mil]
  rect 70x70 hole 39.37: 1(-100,-50)
  round 70 hole 39.37: 2(-100,50) 3(0,-50) 4(0,50) 5(100,-50) 6(100,50)
  silkscreen extent -159,-100 159,100
IMPORTED_IMAGE [mm]
  silkscreen extent 0,-5.02 7.18,0
IND-SMD_L7.2-W6.6_GPSR07X0 [mm]
  rect 2.35x3.5 smd: 1(-2.85,0) 2(2.85,0)
  silkscreen extent -3.3,-3.3 3.3,3.3
LED0805-R-RD [mm]
  rect 1x1.4 smd: 1(1.05,0) 2(-1.05,0)
  silkscreen extent -2.22,-1.04 1.99,1.01
R0402 [mm]
  rect 0.566x0.54 smd: 1(-0.433,0) 2(0.433,0)
  silkscreen extent -0.94,-0.5 0.94,0.5
R0603 [mm]
  rect 0.806x0.864 smd: 1(-0.753,0) 2(0.753,0)
  silkscreen extent -1.39,-0.66 1.39,0.66
R1206 [mm]
  rect 1.208x1.701 smd: 1(-1.479,0) 2(1.479,0)
  silkscreen extent -2.31,-1.08 2.31,1.08
rasberrypi-3-hat-ext [mil]
  round 62 hole 35: 1(0,-100) 2(0,0) 3(100,-100) 4(100,0) 5(200,-100) 6(200,0) 7(300,-100) 8(300,0) 9(400,-100) 10(400,0) 11(500,-100) 12(500,0) 13(600,-100) 14(600,0) 15(700,-100) 16(700,0) 17(800,-100) 18(800,0) 19(900,-100) 20(900,0) 21(1000,-100) 22(1000,0) 25(1200,-100) 26(1200,0) 27(1300,-100) 28(1300,0) 29(1400,-100) 30(1400,0) 31(1500,-100) 32(1500,0) 33(1600,-100) 34(1600,0) 35(1700,-100) 36(1700,0) 37(1800,-100) 38(1800,0) 39(1900,-100) 40(1900,0)
  round 65 hole 35: 23(1100,-100) 24(1100,0)
  round 27.56 hole 11.81: 42(-265.61,-2021.5) 42(-265.61,-91.5) 42(2014.39,-2021.5) 42(2014.39,-91.5) 44(-192,-2064) 44(-192,-134) 44(2088,-2064) 44(2088,-134) 46(-118.39,-2021.5) 46(-118.39,-91.5) 46(2161.61,-2021.5) 46(2161.61,-91.5) 48(-118.39,-1936.5) 48(-118.39,-6.5) 48(2161.61,-1936.5) 48(2161.61,-6.5) 50(-192,-1894) 50(-192,36) 50(2088,-1894) 50(2088,36) 52(-265.61,-1936.5) 52(-265.61,-6.5) 52(2014.39,-1936.5) 52(2014.39,-6.5)
  Board Outline Layer lines w10: -210,-2116.61 2900.23,-2116.61 ; -210,-2116.61 2900.23,-2116.61 ; -210,-2116.61 cw(c-210,-1998.5) -328.11,-1998.5 ccw(c-210,-1998.5) -210,-2116.61 ; -210,88.11 2900.23,88.11 ; -210,88.11 2900.23,88.11 ; -210,88.11 ccw(c-210,-30) -328.11,-30 cw(c-210,-30) -210,88.11 ; 2900.24,-2116.61 ccw(c2900.24,-1998.5) 3018.35,-1998.5 ; 2900.24,-2116.61 ccw(c2900.24,-1998.5) 3018.35,-1998.5 ; 2900.24,88.11 cw(c2900.24,-30) 3018.35,-30 ; 2900.24,88.11 cw(c2900.24,-30) 3018.35,-30 ; 3018.34,-1998.51 3018.34,-30 ; 3018.34,-1998.51 3018.34,-30 ; -328,-1998 -328,-29.5 -328,-1998
  Multi-Layer board cut-out: 2148,-49 2139.88,-19.1 2117.93,2.77 2088,10.77 2058.07,2.77 2036.12,-19.1 2028,-49 2028,-49 2036.12,-78.9 2058.07,-100.77 2088,-108.77 2117.93,-100.77 2139.88,-78.9 2148,-49
  Multi-Layer board cut-out: -132,-49 -140.12,-19.1 -162.07,2.77 -192,10.77 -221.93,2.77 -243.88,-19.1 -252,-49 -252,-49 -243.88,-78.9 -221.93,-100.77 -192,-108.77 -162.07,-100.77 -140.12,-78.9 -132,-49
  Multi-Layer board cut-out: -132,-1979 -140.12,-1949.1 -162.07,-1927.23 -192,-1919.23 -221.93,-1927.23 -243.88,-1949.1 -252,-1979 -252,-1979 -243.88,-2008.9 -221.93,-2030.77 -192,-2038.77 -162.07,-2030.77 -140.12,-2008.9 -132,-1979
  Multi-Layer board cut-out: 2148,-1979 2139.88,-1949.1 2117.93,-1927.23 2088,-1919.23 2058.07,-1927.23 2036.12,-1949.1 2028,-1979 2028,-1979 2036.12,-2008.9 2058.07,-2030.77 2088,-2038.77 2117.93,-2030.77 2139.88,-2008.9 2148,-1979
  Multi-Layer keep-out region: 2148,-49 2139.88,-19.1 2117.93,2.77 2088,10.77 2058.07,2.77 2036.12,-19.1 2028,-49 2028,-49 2036.12,-78.9 2058.07,-100.77 2088,-108.77 2117.93,-100.77 2139.88,-78.9 2148,-49
  Multi-Layer keep-out region: -132,-49 -140.12,-19.1 -162.07,2.77 -192,10.77 -221.93,2.77 -243.88,-19.1 -252,-49 -252,-49 -243.88,-78.9 -221.93,-100.77 -192,-108.77 -162.07,-100.77 -140.12,-78.9 -132,-49
  Multi-Layer keep-out region: -132,-1979 -140.12,-1949.1 -162.07,-1927.23 -192,-1919.23 -221.93,-1927.23 -243.88,-1949.1 -252,-1979 -252,-1979 -243.88,-2008.9 -221.93,-2030.77 -192,-2038.77 -162.07,-2030.77 -140.12,-2008.9 -132,-1979
  Multi-Layer keep-out region: 2148,-1979 2139.88,-1949.1 2117.93,-1927.23 2088,-1919.23 2058.07,-1927.23 2036.12,-1949.1 2028,-1979 2028,-1979 2036.12,-2008.9 2058.07,-2030.77 2088,-2038.77 2117.93,-2030.77 2139.88,-2008.9 2148,-1979
  silkscreen extent -314,-2101 2210,73
rcj-04 [mm]
  oval 3.6x2.5 hole 1.5 slot 2.5 at 0 deg: 1(0,-1.95)
  oval 1.8x3.2 hole 1 slot 2.5 at 90 deg copper offset -0.001,0: 2(0.001,2.55)
  Multi-Layer board cut-out: -5.25,-6 -5.25,-4.3 -5.242,-4.262 -5.221,-4.229 -5.188,-4.208 -5.15,-4.2 -5.15,-4.2 -3.35,-4.2 -3.312,-4.208 -3.279,-4.229 -3.258,-4.262 -3.25,-4.3 -3.25,-4.3 -3.25,-6 -3.258,-6.038 -3.279,-6.071 -3.312,-6.092 -3.35,-6.1 -3.35,-6.1 -5.15,-6.1 -5.188,-6.092 -5.221,-6.071 -5.242,-6.038 -5.25,-6
  Multi-Layer board cut-out: 3.25,-6 3.25,-4.3 3.258,-4.262 3.279,-4.229 3.312,-4.208 3.35,-4.2 3.35,-4.2 5.15,-4.2 5.188,-4.208 5.221,-4.229 5.242,-4.262 5.25,-4.3 5.25,-4.3 5.25,-6 5.242,-6.038 5.221,-6.071 5.188,-6.092 5.15,-6.1 5.15,-6.1 3.35,-6.1 3.312,-6.092 3.279,-6.071 3.258,-6.038 3.25,-6
  Multi-Layer keep-out region: -5.25,-6 -5.25,-4.3 -5.242,-4.262 -5.221,-4.229 -5.188,-4.208 -5.15,-4.2 -5.15,-4.2 -3.35,-4.2 -3.312,-4.208 -3.279,-4.229 -3.258,-4.262 -3.25,-4.3 -3.25,-4.3 -3.25,-6 -3.258,-6.038 -3.279,-6.071 -3.312,-6.092 -3.35,-6.1 -3.35,-6.1 -5.15,-6.1 -5.188,-6.092 -5.221,-6.071 -5.242,-6.038 -5.25,-6
  Multi-Layer keep-out region: 3.25,-6 3.25,-4.3 3.258,-4.262 3.279,-4.229 3.312,-4.208 3.35,-4.2 3.35,-4.2 5.15,-4.2 5.188,-4.208 5.221,-4.229 5.242,-4.262 5.25,-4.3 5.25,-4.3 5.25,-6 5.242,-6.038 5.221,-6.071 5.188,-6.092 5.15,-6.1 5.15,-6.1 3.35,-6.1 3.312,-6.092 3.279,-6.071 3.258,-6.038 3.25,-6
  silkscreen extent -5.2,-15.65 5.2,3.9
SC-75-3_L1.6-W0.8-P1.00-LS1.6-BR [mm]
  rect 0.816x0.4 smd: 1(0.65,-0.5) 2(0.65,0.5) 3(-0.65,0)
  silkscreen extent -0.48,-0.88 0.48,0.88
SMA_L4.4-W2.8-LS5.4-R-RD [mm]
  rect 2.063x1.539 smd: 1(2.504,0) 2(-2.504,0)
  silkscreen extent -3.03,-1.43 2.65,1.43
SOD-123_L2.7-W1.6-LS3.7-RD [mm]
  rect 0.91x1.22 smd: 1(-1.635,0) 2(1.635,0)
  silkscreen extent -1.6,-1 1.38,1
soic-8_l4.9-w3.9-p1.27-ls6.0-bl [mm]
  oval 0.588x2.045 smd: 1(-1.905,-2.772) 2(-0.635,-2.772) 3(0.635,-2.772) 4(1.905,-2.772) 5(1.905,2.772) 6(0.635,2.772) 7(-0.635,2.772) 8(-1.905,2.772)
  silkscreen extent -2.8,-2.92 2.53,1.52
SOIC-8_L4.9-W3.9-P1.27-LS6.0-BL [mm]
  oval 0.588x2.045 smd: 1(-1.905,-2.772) 2(-0.635,-2.772) 3(0.635,-2.772) 4(1.905,-2.772) 5(1.905,2.772) 6(0.635,2.772) 7(-0.635,2.772) 8(-1.905,2.772)
  silkscreen extent -2.8,-2.92 2.53,1.52
SOIC-8_L5.0-W4.0-P1.27-LS6.0-BL [mil]
  oval 22.38x76.78 smd: 1(-75,-106.5) 2(-25,-106.5) 3(25,-106.5) 4(75,-106.5) 5(75,106.5) 6(25,106.5) 7(-25,106.5) 8(-75,106.5)
  silkscreen extent -106,-111 98,75
SOIC-8_L5.0-W4.0-P1.27-LS6.0-BL-EP2.0 [mm]
  oval 0.574x2.038 smd: 1(-1.905,-2.769) 2(-0.635,-2.769) 3(0.635,-2.769) 4(1.905,-2.769) 5(1.905,2.769) 6(0.635,2.769) 7(-0.635,2.769) 8(-1.905,2.769)
  rect 2x2 smd: 9(0,0)
  silkscreen extent -2.79,-2.92 2.53,1.52
SOT-23-3_L2.9-W1.3-P1.90-LS2.4-BR [mm]
  rect 1.25x0.7 smd: 1(1,-0.95) 2(1,0.95) 3(-1,0)
  silkscreen extent -0.73,-1.53 0.73,1.53
SOT-23-3_L2.9-W1.6-P1.90-LS2.8-BR [mm]
  rect 1.07x0.6 smd: 1(1.235,-0.95) 2(1.235,0.95) 3(-1.235,0)
  silkscreen extent -0.88,-1.54 0.88,1.54
SOT-23-6_L2.9-W1.6-P0.95-LS2.8-BR [mm]
  rect 1.1x0.6 smd: 1(1.35,-0.95) 2(1.35,0) 3(1.35,0.95) 4(-1.35,0.95) 5(-1.35,0) 6(-1.35,-0.95)
  silkscreen extent -0.9,-1.78 1.52,1.55
sot-23-8_l3.0-w1.7-p0.65-ls2.8-br [mm]
  oval 1.252x0.364 smd: 1(1.226,-0.975) 2(1.226,-0.325) 3(1.226,0.325) 4(1.226,0.975) 5(-1.226,0.975) 6(-1.226,0.325) 7(-1.226,-0.325) 8(-1.226,-0.975)
  silkscreen extent -0.37,-1.76 1.38,1.53
SOT-363_L2.0-W1.3-P0.65-LS2.1-TL [mm]
  rect 0.7x0.42 smd: 1(-0.92,0.65) 2(-0.92,0) 3(-0.92,-0.65) 4(0.92,-0.65) 5(0.92,0) 6(0.92,0.65)
  silkscreen extent -1.09,-1.1 0.7,1.24
test-point-0.5mm [mm]
  round 1 smd: 1(0,0)
TO-252-2_L6.6-W6.1-P4.58-LS9.9-TL [mm]
  rect 2.409x0.979 smd: 1(-3.424,2.29) 3(-3.423,-2.29)
  rect 5.711x5.548 smd: 2(3.424,0)
  silkscreen extent -1.38,-3.35 4.58,3.35

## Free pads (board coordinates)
  round 1.524 hole 3 unplated: 41(138.309,109.09)
  round 0.7 hole 0.3: 42(136.439,108.011) 44(138.309,106.931) 46(140.179,108.011) 48(140.179,110.17) 50(138.309,111.249) 52(136.439,110.17)

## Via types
v1: diameter 0.5, hole 0.3, Top Layer to Bottom Layer, 164 vias
v2: diameter 1, hole 0.5, Top Layer to Bottom Layer, 30 vias
v3: diameter 2, hole 1, Top Layer to Bottom Layer, 14 vias
v4: diameter 0.61, hole 0.305, Top Layer to Bottom Layer, 8 vias
v5: diameter 0.8, hole 0.4, Top Layer to Bottom Layer, 6 vias

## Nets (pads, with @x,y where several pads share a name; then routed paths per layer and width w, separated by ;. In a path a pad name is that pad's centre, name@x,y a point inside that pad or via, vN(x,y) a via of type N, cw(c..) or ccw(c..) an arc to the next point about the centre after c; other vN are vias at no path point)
1-WIRE: 1W1.3 1W1.7 1W2.3 1W2.7 D5.3 R19.1 U0.7 | length 65.8
  Top Layer w0.5: 1W1.7@103.477,92.912 106.477,92.912 1W1.3@108.277,94.712 108.561,94.996 111.106,94.996 111.426,94.676 D5.3@111.426,94.076 112.077,94.076 112.977,93.176 1W2.7@112.977,92.912 115.977,92.912 1W2.3@117.777,94.712 117.91,94.712 R19.1@119.285,96.087
  Inner2 w0.5: v2(103.548,106.057) 103.548,101.442 107.089,97.901 107.089,95.841 1W1.3@108.422,94.508
  Bottom Layer w0.5: U0.7@100.997,137.922 100.997,108.51 v2@103.474,106.032
$1N4635: R10.1 R11.2 U5.3 | length 4.6
  Top Layer w0.5: U5.3@112.181,122.762 112.181,120.857 R10.1@112.164,120.84 114.768,120.84 R11.2@114.84,120.913
$1N4659: C8.2 U5.4 | length 2.3
  Top Layer w0.5: U5.4@113.451,122.762 113.451,123.325 114.041,123.915 C8.2@114.967,123.915
$1N4694: C9.1 U5.1 | length 7
  Top Layer w0.5: v5@106.966,127.381 107.651,127.381 C9.1@107.784,127.248 ; v5(108.744,123.571) 108.744,123.016 108.998,122.762 U5.1@109.641,122.762
  Bottom Layer w0.5: v5@106.966,127.381 108.744,125.603 v5(108.744,123.571)
  other v5: 106.921,127.381
$1N4920: C9.2 D1.2 U5.8 U6.1
$1N5140: C12.1 R12.1 | length 2
  Top Layer w0.5: R12.1@111.979,131.627 113.814,131.627 C12.1@113.951,131.764
$1N5148: C12.2 C13.2 U5.6 | length 3.9
  Top Layer w0.5: U5.6@112.181,128.301 112.181,130.141 C13.2@112.091,130.23 113.818,130.23 C12.2@113.951,130.364
$1N5310: R13.2 R14.1 U5.5 | length 10.9
  Top Layer w0.5: R14.1@110.193,133.413 R13.2@111.613,133.413 111.613,133.934 111.919,134.239 113.189,134.239 114.967,132.461 114.967,129.817 U5.5@113.451,128.301
$1N7006: Q1.4 Q2.1 R59.2 | length 7.6
  Top Layer w0.5: R59.2@88.476,135.001 88.993,134.484 88.993,134.3 ; Q1.4@88.993,133.684 88.993,134.3 ; v5(89.694,135.001) 88.993,134.3 ; Q2.1@93.057,135.22 93.276,135.001 v5(93.885,135.001)
  Bottom Layer w0.5: v5(89.694,135.001) v5(93.885,135.001)
$1N7063: Q1.1 Q1.2 Q1.3 R16.2 | length 3.4
  Top Layer w0.5: Q1.1@87.093,130.984 Q1.2@88.043,130.984 Q1.3@88.993,130.984 90.23,130.984 R16.2@90.404,130.81
$1N14594: C24.2 U12.4 | length 1.5
  Top Layer w0.5: C24.2@121.534,115.697 121.534,116.905 U12.4@121.723,117.094
$1N14595: C25.1 U12.1 | length 6.3
  Top Layer w0.5: U12.1@121.723,120.904 121.723,121.564 121.952,121.793 v5(122.714,121.793) ; v5(126.143,122.174) C25.1@127.122,122.174
  Bottom Layer w0.5: v5(122.714,121.793) 123.095,122.174 v5(126.143,122.174)
$1N14596: C25.2 D3.2 U12.8 U13.1 | length 3.2
  Top Layer w1.8: U13.1@129.572,127.452 130.262,126.762 D3.2@130.262,124.587
$1N14599: C28.1 R34.1 | length 1.5
  Top Layer w0.5: C28.1@130.399,116.84 130.464,116.905 R34.1@130.464,118.288
$1N14601: C28.2 C29.2 U12.6 | length 3.4
  Top Layer w0.5: U12.6@127.261,118.364 128.874,118.364 129.067,118.557 129.067,117.135 C28.2@129.002,117.07
$1N14603: R39.2 R66.1 U12.5 | length 10.1
  Top Layer w0.5: U12.5@127.261,117.094 127.261,116.611 128.048,115.824 130.969,115.824 131.35,116.205 131.35,118.973 131.809,119.432 R39.2@132.112,119.432 R66.1@132.112,120.725
$1N55959: D2.1 Q3.1 R17.2 R18.2 | length 6.5
  Top Layer w0.5: D2.1@138.319,102.235 138.319,101.286 138.819,100.786 R17.2@139.732,100.786 140.371,100.147 ; Q3.1@140.371,98.166 140.371,100.147 ; R18.2@141.129,100.847 140.43,100.147 140.371,100.147
$1N59627: CN8.2 R32.1 R33.2 U12.3 | length 29.3
  Top Layer w0.5: U12.3@121.723,118.364 121.605,118.246 R32.1@119.666,118.246 118.904,117.484 118.904,116.078 120.809,114.173 125.88,114.173 ; R33.2@125.88,115.57 125.88,114.173 ; CN8.2@138.462,118.237 138.462,116.078 136.557,114.173 125.88,114.173
$1N62787: R91.1 U23.7 WP0.1 | length 5.9
  Top Layer w0.5: WP0.1@88.592,128.465 88.651,128.524 90.023,128.524 R91.1@90.404,128.143 90.456,128.091 90.456,126.347 91.454,125.349 U23.7@92.145,125.349
$1N73953: CN7.1 CN7.2 R66.2 | length 10.2
  Top Layer w0.5: R66.2@132.112,121.464 132.187,121.539 132.874,121.539 134.652,119.761 137.192,119.761 CN7.2@138.462,121.031 ; CN7.2@138.462,121.158 CN7.1@138.462,123.698
$1N74122: CN7.4 R67.1 | length 4.2
  Top Layer w0.5: R67.1@132.62,123.392 133.688,123.392 CN7.4@135.922,121.158
$2N529: Q7.1 R20.2 R21.2 | length 2.7
  Top Layer w0.5: R21.2@143.848,110.363 R20.2@143.848,109.093 143.848,107.689 Q7.1@143.857,107.68
$2N530: Q4.4 Q7.3 R22.1 | length 9.3
  Top Layer w0.5: Q7.3@142.907,105.68 143.923,104.664 143.923,104.267 148.495,104.267 149.384,103.378 Q4.4@149.384,101.749
$2N536: F5.1 R23.2 U20.8 | length 7.6
  Top Layer w0.3: F5.1@149.84,111.379 149.84,110.333 151.838,108.335 U20.8@151.838,107.525
  Top Layer w2: F5.1@149.84,111.379 150.702,112.241 R23.2@152.368,112.241
$2N538: F5.2 Q4.5 Q4.6 Q4.7 Q4.8 | length 6.4
  Top Layer w2: F5.2@146.147,112.096 146.134,112.083 146.134,108.004 Q4.7@146.844,107.293 Q4.6@148.114,107.293
$2N1597: Q8.4 Q16.3 R27.1 | length 7.1
  Top Layer w0.5: R27.1@114.205,105.485 113.264,105.485 112.688,104.909 Q8.4@112.688,102.648 114.697,102.648 Q16.3@115.475,101.87
$2N1603: F6.1 R26.2 U18.8 | length 13.8
  Top Layer w0.3: R26.2@100.698,96.901 100.956,97.159 U18.8@100.956,99.866
  Top Layer w2: R26.2@100.698,96.901 101.632,96.901 102.707,97.976 102.707,103.056 103.716,104.065 F6.1@105.442,104.065
$2N1605: F6.2 Q8.5 Q8.6 Q8.7 Q8.8
$2N1610: Q9.4 Q20.3 R30.1 | length 7.6
  Top Layer w0.5: R30.1@114.205,114.502 113.01,114.502 112.688,114.18 Q9.4@112.688,111.654 112.688,111.245 112.779,111.154 115.081,111.154 Q20.3@115.475,110.76
$2N1616: F7.1 R29.2 U19.8 | length 10
  Top Layer w0.3: U19.8@100.956,111.55 100.956,109.47 R29.2@101.587,108.839
  Top Layer w2: R29.2@101.587,108.839 102.648,109.9 102.648,112.395 103.589,113.336 F7.1@105.315,113.336
$2N1618: F7.2 Q9.5 Q9.6 Q9.7 Q9.8
$2N3421: Q11.1 R40.2 R41.2 | length 3.2
  Top Layer w0.5: R40.2@141.689,123.317 R41.2@142.982,123.317 142.982,122.909 Q11.1@144.023,121.868
$2N3422: Q10.4 Q11.3 R42.1 | length 9.4
  Top Layer w0.5: Q11.3@143.073,119.868 143.923,119.019 143.923,118.11 148.495,118.11 149.384,117.221 Q10.4@149.384,115.719
$2N3428: F8.1 R43.2 U21.8 | length 4.3
  Top Layer w0.3: F8.1@149.84,124.968 149.84,124.004 151.838,122.006 U21.8@151.838,121.495
$2N3430: F8.2 Q10.5 Q10.6 Q10.7 Q10.8 | length 5.7
  Top Layer w2: 146.046,121.314 F8.2@146.046,125.701 ; Q10.7@146.844,121.263 Q10.6@148.114,121.263
$2N4457: Q15.1 R48.2 R49.2 | length 3.2
  Top Layer w0.5: R48.2@141.503,134.253 143.36,134.253 R49.2@143.378,134.271 ; Q15.1@143.395,132.951 R49.2@143.395,134.288
$2N4458: Q14.4 Q15.3 R50.1 | length 8.7
  Top Layer w0.5: Q15.3@142.444,130.937 143.497,130.937 R50.1@143.949,130.485 ; R50.1@143.923,130.481 148.951,130.481 149.384,130.048 Q14.4@149.384,128.673
$2N4464: F10.1 R51.2 U22.8 | length 6.5
  Top Layer w0.3: U22.8@151.965,134.449 151.965,136.521 R51.2@152.477,137.033
  Top Layer w1.5: R51.2@152.823,137.287 152.823,138.401 F10.1@154.666,140.244
$2N4466: F10.2 Q14.5 Q14.6 Q14.7 Q14.8 | length 8.3
  Top Layer w2: Q14.7@146.844,134.217 Q14.6@148.114,134.217 ; 147.733,134.471 150.452,137.19 F10.2@150.452,140.335
$2N24815: Q16.1 R53.2 R54.2 | length 2.8
  Top Layer w0.5: Q16.1@116.425,103.87 116.425,105.396 R54.2@116.439,105.41 R53.2@116.439,106.68
$2N25317: Q20.1 R55.2 R56.2 | length 5.3
  Top Layer w0.5: R55.2@115.983,114.502 115.983,113.202 116.425,112.76 116.416,112.751 R56.2@116.416,109.347
$2N39826: LED4.1 R64.2 | length 2
  Top Layer w0.5: LED4.1@88.927,94.996 89.47,94.453 R64.2@90.741,94.453
$2N39921: LED5.1 R65.2 | length 2.1
  Top Layer w0.5: LED5.1@88.8,108.532 90.064,108.532 90.317,108.279 R65.2@90.837,108.279
$2N39926: PWM2.2 R26.1 R64.1 U18.7 | length 15.4
  Top Layer w0.3: R26.1@97.74,96.901 98.375,97.536 99.233,97.536 100.306,98.609 U18.7@100.306,99.866
  Top Layer w0.5: R64.1@90.723,95.354 90.723,96.018 93.345,98.64
  Top Layer w2: PWM2.2@94.142,101.147 94.142,98.925 96.139,96.927 R26.1@97.609,96.927
$2N39937: PWM1.2 R29.1 R65.1 U19.7 | length 16.7
  Top Layer w0.3: R29.1@98.629,108.839 100.306,110.516 U19.7@100.306,111.55
  Top Layer w0.5: R65.1@90.837,109.145 92.055,110.363 93.123,110.363
  Top Layer w2: PWM1.2@94.527,115.262 93.827,114.562 93.827,110.548 95.536,108.839 R29.1@98.629,108.839
$2N40038: LED1.1 R61.2 | length 2.8
  Top Layer w0.5: R61.2@163.227,101.294 165.808,101.294 LED1.1@165.987,101.473
$2N40133: LED2.1 R62.2 | length 3
  Top Layer w0.5: R62.2@163.1,115.391 165.681,115.391 LED2.1@165.987,115.697
$2N40233: DC3.4 R51.1 R86.2 U22.7 | length 15.8
  Top Layer w0.3: U22.7@152.615,134.449 152.615,135.636 154.038,135.636 R51.1@155.435,137.033
  Top Layer w0.5: R86.2@158.095,130.158 158.095,136.092 158.465,136.462 DC3.4@159.127,136.462 ; DC3.4@159.055,136.534 DC3.4@159.127,136.605
  Top Layer w2: R51.1@155.226,136.779 158.81,136.779 159.055,136.534 DC3.4@159.127,136.462
$2N40244: DC2.4 R43.1 R62.1 U21.7 | length 17.5
  Top Layer w0.3: U21.7@152.488,121.495 152.488,122.865 155.325,125.702 R43.1@155.325,125.872
  Top Layer w0.5: DC2.4@159.127,122.462 163.1,118.489 R62.1@163.1,116.257
  Top Layer w2: 157.469,125.872 159.127,124.214 DC2.4@159.127,122.462
$2N40255: DC1.4 R23.1 R61.1 U20.7 | length 20.1
  Top Layer w0.3: U20.7@152.488,107.525 152.488,109.403 R23.1@155.325,112.241
  Top Layer w0.5: DC1.4@159.127,108.462 159.127,108.24 163.227,104.14 R61.1@163.227,102.16
  Top Layer w2: R23.1@155.325,112.241 156.777,112.241 159.127,109.891 DC1.4@159.127,108.462
$2N49861: Q19.1 R86.1 R87.2 | length 3.3
  Top Layer w0.5: R87.2@158.961,128.888 R86.1@158.961,130.158 160.785,130.158 Q19.1@160.926,130.017
$2N50059: LED13.2 Q19.3 | length 10.7
  Top Layer w0.5: Q19.3@162.226,129.517 162.465,129.278 162.465,128.086 164.411,126.139 166.811,126.139 168.087,127.415 LED13.2@168.087,129.605
$2N57491: LED13.1 R88.2 | length 2.8
  Top Layer w0.5: R88.2@163.481,128.787 165.168,128.787 LED13.1@165.987,129.605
